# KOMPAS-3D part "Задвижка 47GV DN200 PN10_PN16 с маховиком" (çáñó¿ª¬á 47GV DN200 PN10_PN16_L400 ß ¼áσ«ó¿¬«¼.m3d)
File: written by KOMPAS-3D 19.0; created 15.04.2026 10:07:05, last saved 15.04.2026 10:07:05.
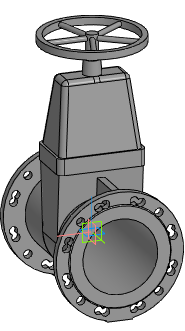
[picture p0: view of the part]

Document properties: Автор: Евгений; Полное имя файла: Z:\3.Личные\kachalov\3d для проектировщиков\2.1 Тип 47GV, 47GV.Z\Задвижка 47GV_DN40-DN600\stp_Задвижка 47GV\Задвижка 47GV DN200 PN10_PN16_L400 с маховиком.m3d

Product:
- Part/product: Задвижка 47GV DN200 PN10_PN16 с маховиком

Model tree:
1. Операция без истории:1  (labels: Задвижка 47GV DN200 PN10_PN16 с маховиком)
